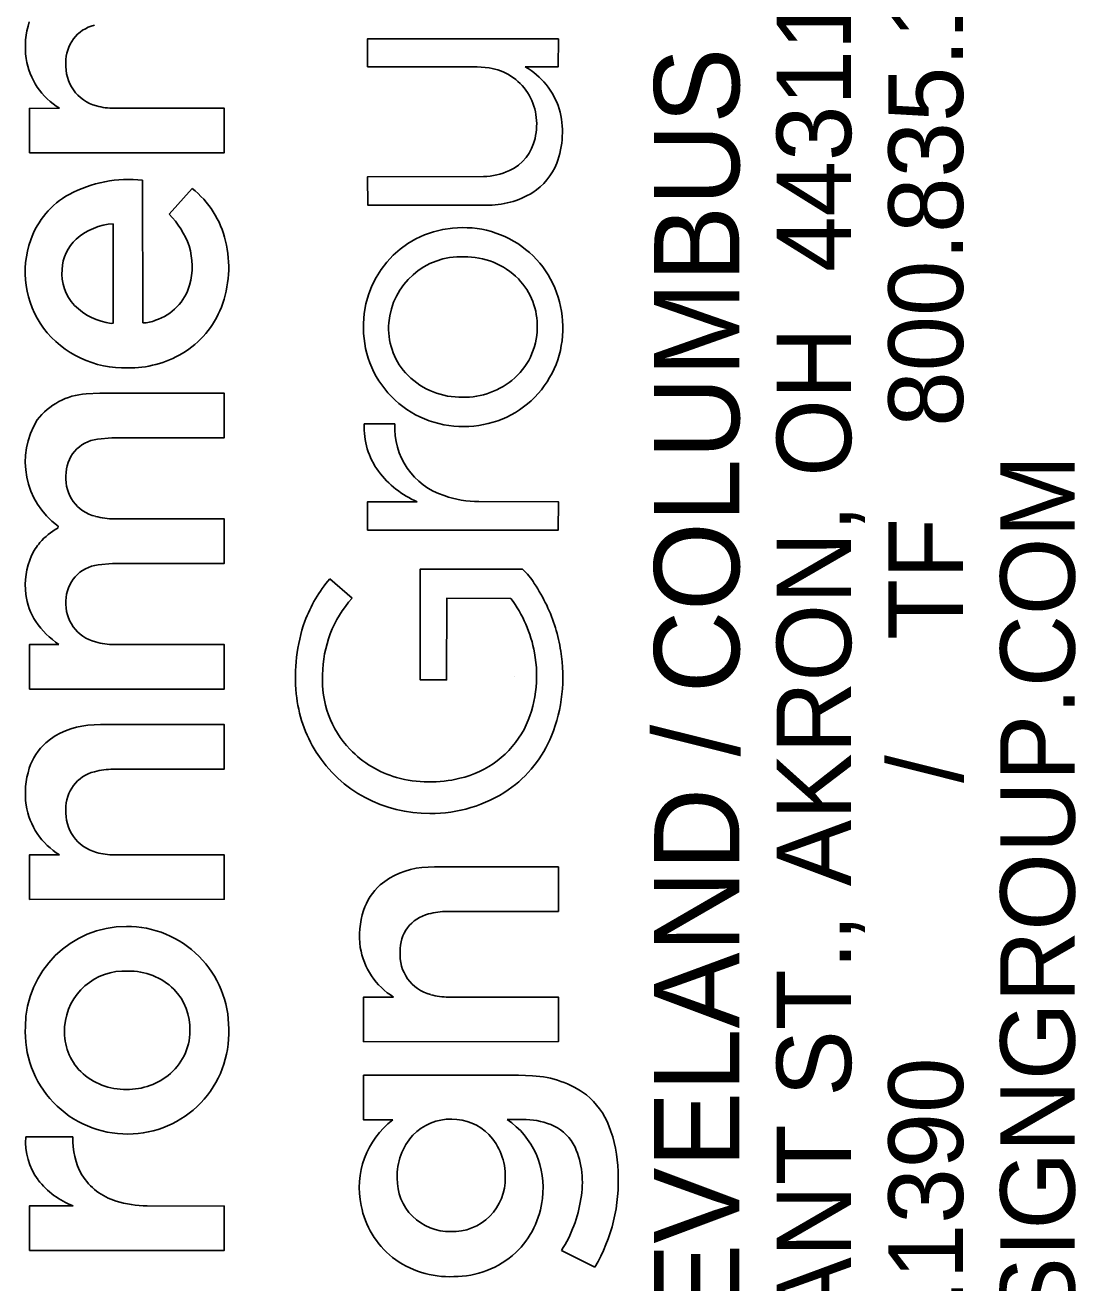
# Model space of a CAD drawing. Extents: x -1.7 to 34, y -55.6 to 22.
# Drawn here: x 32.423 to 33.125, y 3.594 to 4.436 of the extents above; entities that cross this region are included whole.
import ezdxf

# ---------------------------------------------------------------- set-up
doc = ezdxf.new("R2010")
doc.units = 0
doc.layers.add('SH_Data', color=7, linetype='Continuous')

msp = doc.modelspace()

# ---------------------------------------------------------------- linework, layer by layer
at = {"layer": 'SH_Data'}
for p, q in [((32.65152, 4.40801), (32.65153, 4.42672)), ((32.65153, 4.42672), (32.7791, 4.42664)), ((32.7791, 4.42664), (32.77908, 4.40796)), ((32.7249, 4.40796), (32.65152, 4.40801)), ((32.7328, 4.40727), (32.7249, 4.40796)), ((32.77908, 4.40796), (32.75689, 4.40796)), ((32.42542, 4.38016), (32.44552, 4.38021)), ((32.42542, 4.35035), (32.42542, 4.38016)), ((32.48222, 4.38021), (32.55569, 4.38021)), ((32.55569, 4.38021), (32.55571, 4.35045)), ((32.55571, 4.35045), (32.42542, 4.35035)), ((32.65154, 4.33443), (32.72905, 4.3345)), ((32.65165, 4.31543), (32.65154, 4.33443)), ((32.50108, 4.33209), (32.50118, 4.23657)), ((32.51882, 4.30927), (32.53422, 4.32662)), ((32.73073, 4.31543), (32.65165, 4.31543)), ((32.48144, 4.23644), (32.48144, 4.30296)), ((32.48016, 4.23628), (32.48144, 4.23644)), ((32.46329, 4.18915), (32.47259, 4.18968)), ((32.47259, 4.18968), (32.55557, 4.18968)), ((32.55557, 4.18968), (32.55571, 4.15982)), ((32.64932, 4.16907), (32.66978, 4.16907)), ((32.48058, 4.15981), (32.47102, 4.15881)), ((32.55571, 4.15982), (32.48058, 4.15981)), ((32.65152, 4.11699), (32.68476, 4.117)), ((32.65152, 4.098), (32.65152, 4.11699)), ((32.72605, 4.11703), (32.7791, 4.11696)), ((32.7791, 4.11696), (32.77903, 4.098)), ((32.44443, 4.09922), (32.44455, 4.10072)), ((32.48218, 4.10553), (32.55571, 4.10548)), ((32.55571, 4.10548), (32.55571, 4.07568)), ((32.77903, 4.098), (32.65152, 4.098)), ((32.4809, 4.07567), (32.47143, 4.07474)), ((32.55571, 4.07568), (32.4809, 4.07567)), ((32.62636, 4.06548), (32.64114, 4.05241)), ((32.6868, 4.07185), (32.75516, 4.07192)), ((32.6868, 3.99778), (32.6868, 4.07185)), ((32.70448, 4.05241), (32.70432, 3.99775)), ((32.74737, 4.05227), (32.70448, 4.05241)), ((32.42542, 3.99152), (32.42545, 4.02138)), ((32.42545, 4.02138), (32.44515, 4.02138)), ((32.48206, 4.02138), (32.55571, 4.02136)), ((32.55571, 4.02136), (32.55571, 3.99156)), ((32.70432, 3.99775), (32.6868, 3.99778)), ((32.75, 4), (32.75, 4)), ((32.55571, 3.99156), (32.42542, 3.99152)), ((32.46439, 3.96736), (32.47289, 3.96783)), ((32.47289, 3.96783), (32.55571, 3.96783)), ((32.55571, 3.96783), (32.55571, 3.93804)), ((32.55571, 3.93804), (32.4814, 3.93796)), ((32.42542, 3.88066), (32.44552, 3.88071)), ((32.42542, 3.85086), (32.42542, 3.88066)), ((32.48222, 3.88071), (32.55569, 3.88071)), ((32.55569, 3.88071), (32.55571, 3.85096)), ((32.68784, 3.8722), (32.69634, 3.87266)), ((32.69634, 3.87266), (32.77916, 3.87266)), ((32.77916, 3.87266), (32.77917, 3.84287)), ((32.55571, 3.85096), (32.42542, 3.85086)), ((32.77917, 3.84287), (32.70485, 3.8428)), ((32.64888, 3.7855), (32.66897, 3.78555)), ((32.64888, 3.75569), (32.64888, 3.7855)), ((32.70568, 3.78555), (32.77915, 3.78555)), ((32.77915, 3.78555), (32.77917, 3.75579)), ((32.77917, 3.75579), (32.64888, 3.75569)), ((32.6489, 3.70336), (32.64889, 3.73322)), ((32.64889, 3.73322), (32.75236, 3.73322)), ((32.75236, 3.73322), (32.76191, 3.73285)), ((32.66836, 3.70336), (32.6489, 3.70336)), ((32.75763, 3.70356), (32.74487, 3.70361)), ((32.42299, 3.69193), (32.45454, 3.69193)), ((32.42542, 3.64577), (32.45473, 3.64579)), ((32.42542, 3.61593), (32.42542, 3.64577)), ((32.50413, 3.64581), (32.55571, 3.64573)), ((32.55571, 3.64573), (32.55565, 3.61593)), ((32.55565, 3.61593), (32.42542, 3.61593)), ((32.8036, 3.60491), (32.7812, 3.61598))]:
    msp.add_line(p, q, dxfattribs=at)
for points in [[(32.7328, 4.40727), (32.7249, 4.40796), (32.65152, 4.40801), (32.65153, 4.42672), (32.7791, 4.42664), (32.77908, 4.40796), (32.75689, 4.40796)], [(32.42542, 4.35035), (32.42542, 4.38016), (32.44552, 4.38021)], [(32.48222, 4.38021), (32.55569, 4.38021), (32.55571, 4.35045), (32.42542, 4.35035)], [(32.73073, 4.31543), (32.65165, 4.31543), (32.65154, 4.33443), (32.72905, 4.3345)], [(32.50108, 4.33209), (32.50118, 4.23657)], [(32.51882, 4.30927), (32.53422, 4.32662)], [(32.48016, 4.23628), (32.48144, 4.23644), (32.48144, 4.30296)], [(32.46329, 4.18915), (32.47259, 4.18968), (32.55557, 4.18968), (32.55571, 4.15982), (32.48058, 4.15981), (32.47102, 4.15881)], [(32.64932, 4.16907), (32.66978, 4.16907)], [(32.72605, 4.11703), (32.7791, 4.11696), (32.77903, 4.098), (32.65152, 4.098)], [(32.65152, 4.098), (32.65152, 4.11699), (32.68476, 4.117)], [(32.44443, 4.09922), (32.44455, 4.10072)], [(32.48218, 4.10553), (32.55571, 4.10548), (32.55571, 4.07568), (32.4809, 4.07567), (32.47143, 4.07474)], [(32.62636, 4.06548), (32.64114, 4.05241)], [(32.74737, 4.05227), (32.70448, 4.05241), (32.70432, 3.99775), (32.6868, 3.99778), (32.6868, 4.07185), (32.75516, 4.07192)], [(32.42542, 3.99152), (32.42545, 4.02138), (32.44515, 4.02138)], [(32.48206, 4.02138), (32.55571, 4.02136), (32.55571, 3.99156), (32.42542, 3.99152)], [(32.46439, 3.96736), (32.47289, 3.96783), (32.55571, 3.96783), (32.55571, 3.93804), (32.4814, 3.93796)], [(32.42542, 3.85086), (32.42542, 3.88066), (32.44552, 3.88071)], [(32.48222, 3.88071), (32.55569, 3.88071), (32.55571, 3.85096), (32.42542, 3.85086)], [(32.68784, 3.8722), (32.69634, 3.87266), (32.77916, 3.87266), (32.77917, 3.84287), (32.70485, 3.8428)], [(32.64888, 3.75569), (32.64888, 3.7855), (32.66897, 3.78555)], [(32.70568, 3.78555), (32.77915, 3.78555), (32.77917, 3.75579), (32.64888, 3.75569)], [(32.66836, 3.70336), (32.6489, 3.70336), (32.64889, 3.73322), (32.75236, 3.73322), (32.76191, 3.73285)], [(32.75763, 3.70356), (32.74487, 3.70361)], [(32.42299, 3.69193), (32.45454, 3.69193)], [(32.50413, 3.64581), (32.55571, 3.64573), (32.55565, 3.61593), (32.42542, 3.61593)], [(32.42542, 3.61593), (32.42542, 3.64577), (32.45473, 3.64579)], [(32.8036, 3.60491), (32.7812, 3.61598)]]:
    msp.add_lwpolyline(points, dxfattribs=at)
for centre, radius, start, end in [((32.47872, 4.42108), 0.05602, 162.27398, 187.79173), ((32.47872, 4.42108), 0.05602, 162.27398, 187.79173), ((32.47482, 4.41155), 0.02498, 103.68683, 182.21395), ((32.47482, 4.41155), 0.02498, 103.68683, 182.21395), ((32.47027, 4.4209), 0.04763, 188.96462, 238.69865), ((32.47027, 4.4209), 0.04763, 188.96462, 238.69865), ((32.47735, 4.40846), 0.02757, 175.58441, 255.13816), ((32.47735, 4.40846), 0.02757, 175.58441, 255.13816), ((32.72711, 4.36998), 0.03772, 33.50082, 81.32954), ((32.72711, 4.36998), 0.03772, 33.50082, 81.32954), ((32.73239, 4.36485), 0.04959, 17.62209, 60.38974), ((32.73239, 4.36485), 0.04959, 17.62209, 60.38974), ((32.72414, 4.3695), 0.04048, 346.56179, 31.75389), ((32.72414, 4.3695), 0.04048, 346.56179, 31.75389), ((32.48183, 4.42235), 0.04215, 254.08913, 270.52838), ((32.48183, 4.42235), 0.04215, 254.08913, 270.52838), ((32.72343, 4.36415), 0.05838, 339.16197, 15.61485), ((32.72343, 4.36415), 0.05838, 339.16197, 15.61485), ((32.73371, 4.36616), 0.03042, 294.63214, 348.48625), ((32.73371, 4.36616), 0.03042, 294.63214, 348.48625), ((32.739, 4.35901), 0.04201, 303.10391, 338.15613), ((32.739, 4.35901), 0.04201, 303.10391, 338.15613), ((32.72747, 4.38081), 0.04633, 271.95199, 294.08943), ((32.72747, 4.38081), 0.04633, 271.95199, 294.08943), ((32.49176, 4.24874), 0.08387, 83.62118, 118.28448), ((32.49176, 4.24874), 0.08387, 83.62118, 118.28448), ((32.49399, 4.2763), 0.06443, 13.53275, 51.36266), ((32.49399, 4.2763), 0.06443, 13.53275, 51.36266), ((32.47894, 4.27368), 0.05583, 118.82935, 160.62242), ((32.47894, 4.27368), 0.05583, 118.82935, 160.62242), ((32.7321, 4.37256), 0.05715, 268.62699, 301.47779), ((32.7321, 4.37256), 0.05715, 268.62699, 301.47779), ((32.48033, 4.27018), 0.05485, 19.0387, 45.44322), ((32.48033, 4.27018), 0.05485, 19.0387, 45.44322), ((32.4844, 4.26071), 0.04236, 94.01311, 130.88062), ((32.4844, 4.26071), 0.04236, 94.01311, 130.88062), ((32.71435, 4.23484), 0.06552, 89.48213, 178.77752), ((32.71435, 4.23484), 0.06552, 89.48213, 178.77752), ((32.71582, 4.23414), 0.06623, 0.42265, 90.7613), ((32.71582, 4.23414), 0.06623, 0.42265, 90.7613), ((32.48697, 4.27074), 0.06438, 160.52138, 215.78155), ((32.48697, 4.27074), 0.06438, 160.52138, 215.78155), ((32.47703, 4.2709), 0.02985, 132.98553, 177.1802), ((32.47703, 4.2709), 0.02985, 132.98553, 177.1802), ((32.48724, 4.27433), 0.04701, 344.60723, 17.00675), ((32.48724, 4.27433), 0.04701, 344.60723, 17.00675), ((32.48289, 4.27384), 0.0758, 339.35431, 13.37708), ((32.48289, 4.27384), 0.0758, 339.35431, 13.37708), ((32.71397, 4.23244), 0.04846, 87.68827, 175.01696), ((32.71397, 4.23244), 0.04846, 87.68827, 175.01696), ((32.71659, 4.23036), 0.05052, 44.91202, 90.75914), ((32.71659, 4.23036), 0.05052, 44.91202, 90.75914), ((32.47824, 4.26966), 0.03114, 175.00138, 223.2876), ((32.47824, 4.26966), 0.03114, 175.00138, 223.2876), ((32.49895, 4.27177), 0.03504, 288.01084, 343.55364), ((32.49895, 4.27177), 0.03504, 288.01084, 343.55364), ((32.71955, 4.23452), 0.04549, 358.32279, 43.83486), ((32.71955, 4.23452), 0.04549, 358.32279, 43.83486), ((32.48546, 4.27826), 0.04232, 225.06454, 262.79701), ((32.48546, 4.27826), 0.04232, 225.06454, 262.79701), ((32.49548, 4.26982), 0.0626, 300.94393, 338.73223), ((32.49548, 4.26982), 0.0626, 300.94393, 338.73223), ((32.48908, 4.27516), 0.06872, 217.74341, 271.65606), ((32.48908, 4.27516), 0.06872, 217.74341, 271.65606), ((32.50129, 4.25678), 0.02021, 269.70042, 294.87295), ((32.50129, 4.25678), 0.02021, 269.70042, 294.87295), ((32.71483, 4.2334), 0.06606, 177.53728, 270.94524), ((32.71483, 4.2334), 0.06606, 177.53728, 270.94524), ((32.71085, 4.23311), 0.0453, 175.51467, 221.42047), ((32.71085, 4.23311), 0.0453, 175.51467, 221.42047), ((32.71671, 4.23271), 0.06536, 269.30834, 1.67905), ((32.71671, 4.23271), 0.06536, 269.30834, 1.67905), ((32.71931, 4.23374), 0.04572, 308.90382, 359.30947), ((32.71931, 4.23374), 0.04572, 308.90382, 359.30947), ((32.49204, 4.27702), 0.07055, 269.20529, 300.33566), ((32.49204, 4.27702), 0.07055, 269.20529, 300.33566), ((32.71399, 4.23734), 0.05046, 222.66255, 268.37331), ((32.71399, 4.23734), 0.05046, 222.66255, 268.37331), ((32.71567, 4.23859), 0.05178, 266.55312, 308.67253), ((32.71567, 4.23859), 0.05178, 266.55312, 308.67253), ((32.46638, 4.14404), 0.04521, 93.91118, 142.30723), ((32.46638, 4.14404), 0.04521, 93.91118, 142.30723), ((32.47585, 4.14373), 0.05319, 148.28793, 233.9556), ((32.47585, 4.14373), 0.05319, 148.28793, 233.9556), ((32.69878, 4.16662), 0.04952, 177.16211, 216.28024), ((32.69878, 4.16662), 0.04952, 177.16211, 216.28024), ((32.71735, 4.16638), 0.04764, 176.76988, 252.15044), ((32.71735, 4.16638), 0.04764, 176.76988, 252.15044), ((32.47384, 4.13499), 0.02399, 96.75763, 181.6251), ((32.47384, 4.13499), 0.02399, 96.75763, 181.6251), ((32.47577, 4.13241), 0.02597, 175.81573, 256.16716), ((32.47577, 4.13241), 0.02597, 175.81573, 256.16716), ((32.70975, 4.17555), 0.06366, 216.91526, 246.88619), ((32.70975, 4.17555), 0.06366, 216.91526, 246.88619), ((32.7269, 4.19175), 0.07473, 251.13884, 269.34694), ((32.7269, 4.19175), 0.07473, 251.13884, 269.34694), ((32.4817, 4.15053), 0.04501, 254.34629, 270.61033), ((32.4817, 4.15053), 0.04501, 254.34629, 270.61033), ((32.4638, 4.06267), 0.04137, 117.91625, 139.24296), ((32.4638, 4.06267), 0.04137, 117.91625, 139.24296), ((32.46194, 4.06452), 0.03875, 139.52447, 154.84698), ((32.46194, 4.06452), 0.03875, 139.52447, 154.84698), ((32.47144, 4.0612), 0.04877, 156.06382, 187.3493), ((32.47144, 4.0612), 0.04877, 156.06382, 187.3493), ((32.47421, 4.05056), 0.02434, 96.5532, 179.94902), ((32.47421, 4.05056), 0.02434, 96.5532, 179.94902), ((32.70163, 4.00187), 0.09855, 139.79476, 159.13696), ((32.70163, 4.00187), 0.09855, 139.79476, 159.13696), ((32.72498, 4.03937), 0.04438, 30.98913, 47.16099), ((32.72498, 4.03937), 0.04438, 30.98913, 47.16099), ((32.67091, 4.00018), 0.11106, 25.30315, 33.96179), ((32.67091, 4.00018), 0.11106, 25.30315, 33.96179), ((32.46461, 4.05974), 0.04181, 186.5579, 213.38846), ((32.46461, 4.05974), 0.04181, 186.5579, 213.38846), ((32.47608, 4.04863), 0.02628, 175.722, 255.78627), ((32.47608, 4.04863), 0.02628, 175.722, 255.78627), ((32.69899, 4.00079), 0.07753, 138.25804, 179.70064), ((32.69899, 4.00079), 0.07753, 138.25804, 179.70064), ((32.67889, 4.00099), 0.08556, 10.07509, 36.83189), ((32.67889, 4.00099), 0.08556, 10.07509, 36.83189), ((32.6704, 3.99987), 0.11166, 8.80339, 25.33484), ((32.6704, 3.99987), 0.11166, 8.80339, 25.33484), ((32.47886, 4.07078), 0.0598, 214.70433, 235.68724), ((32.47886, 4.07078), 0.0598, 214.70433, 235.68724), ((32.7187, 3.99968), 0.11536, 161.14379, 185.62812), ((32.7187, 3.99968), 0.11536, 161.14379, 185.62812), ((32.48195, 4.06518), 0.0438, 253.66719, 270.14979), ((32.48195, 4.06518), 0.0438, 253.66719, 270.14979), ((32.68425, 4.00057), 0.08036, 333.46689, 11.03668), ((32.68425, 4.00057), 0.08036, 333.46689, 11.03668), ((32.67564, 3.99977), 0.10649, 338.28866, 9.28548), ((32.67564, 3.99977), 0.10649, 338.28866, 9.28548), ((32.68811, 3.99732), 0.06676, 176.66577, 223.6912), ((32.68811, 3.99732), 0.06676, 176.66577, 223.6912), ((32.69336, 3.99699), 0.08987, 185.50773, 212.01294), ((32.69336, 3.99699), 0.08987, 185.50773, 212.01294), ((32.46871, 3.91767), 0.04988, 94.97056, 130.22484), ((32.46871, 3.91767), 0.04988, 94.97056, 130.22484), ((32.69868, 3.99547), 0.0652, 282.88151, 331.81475), ((32.69868, 3.99547), 0.0652, 282.88151, 331.81475), ((32.46348, 3.92602), 0.04016, 132.22383, 161.68229), ((32.46348, 3.92602), 0.04016, 132.22383, 161.68229), ((32.69835, 3.99168), 0.08241, 305.03061, 337.67573), ((32.69835, 3.99168), 0.08241, 305.03061, 337.67573), ((32.69211, 3.99748), 0.08908, 212.70222, 270.71399), ((32.69211, 3.99748), 0.08908, 212.70222, 270.71399), ((32.69045, 4.00011), 0.07039, 224.02147, 253.88), ((32.69045, 4.00011), 0.07039, 224.02147, 253.88), ((32.47872, 3.92158), 0.05602, 162.27398, 187.79173), ((32.47872, 3.92158), 0.05602, 162.27398, 187.79173), ((32.47482, 3.91206), 0.02498, 103.68683, 182.21395), ((32.47482, 3.91206), 0.02498, 103.68683, 182.21395), ((32.48108, 3.89196), 0.04601, 89.60515, 105.33026), ((32.48108, 3.89196), 0.04601, 89.60515, 105.33026), ((32.69318, 4.01254), 0.08309, 254.45353, 283.9512), ((32.69318, 4.01254), 0.08309, 254.45353, 283.9512), ((32.69429, 3.99979), 0.09138, 269.3273, 304.19632), ((32.69429, 3.99979), 0.09138, 269.3273, 304.19632), ((32.47027, 3.92141), 0.04763, 188.96462, 238.69865), ((32.47027, 3.92141), 0.04763, 188.96462, 238.69865), ((32.47735, 3.90897), 0.02757, 175.58441, 255.13816), ((32.47735, 3.90897), 0.02757, 175.58441, 255.13816), ((32.48183, 3.92286), 0.04215, 254.08913, 270.52838), ((32.48183, 3.92286), 0.04215, 254.08913, 270.52838), ((32.69216, 3.82251), 0.04988, 94.97056, 130.22484), ((32.69216, 3.82251), 0.04988, 94.97056, 130.22484), ((32.68694, 3.83085), 0.04016, 132.22383, 161.68229), ((32.68694, 3.83085), 0.04016, 132.22383, 161.68229), ((32.70217, 3.82642), 0.05602, 162.27398, 187.79173), ((32.70217, 3.82642), 0.05602, 162.27398, 187.79173), ((32.69828, 3.81689), 0.02498, 103.68683, 182.21395), ((32.69828, 3.81689), 0.02498, 103.68683, 182.21395), ((32.70453, 3.79679), 0.04601, 89.60515, 105.33026), ((32.70453, 3.79679), 0.04601, 89.60515, 105.33026), ((32.49014, 3.76543), 0.0674, 89.84756, 179.64047), ((32.49014, 3.76543), 0.0674, 89.84756, 179.64047), ((32.49057, 3.76474), 0.0681, 359.54009, 90.21138), ((32.49057, 3.76474), 0.0681, 359.54009, 90.21138), ((32.69372, 3.82624), 0.04763, 188.96462, 238.69865), ((32.69372, 3.82624), 0.04763, 188.96462, 238.69865), ((32.7008, 3.81381), 0.02757, 175.58441, 255.13816), ((32.7008, 3.81381), 0.02757, 175.58441, 255.13816), ((32.48923, 3.76263), 0.0404, 87.04809, 175.57259), ((32.48923, 3.76263), 0.0404, 87.04809, 175.57259), ((32.49204, 3.75999), 0.04299, 45.84264, 90.98008), ((32.49204, 3.75999), 0.04299, 45.84264, 90.98008), ((32.49458, 3.76421), 0.03821, 357.88569, 44.15902), ((32.49458, 3.76421), 0.03821, 357.88569, 44.15902), ((32.70529, 3.82769), 0.04215, 254.08913, 270.52838), ((32.70529, 3.82769), 0.04215, 254.08913, 270.52838), ((32.49083, 3.76209), 0.06819, 176.8344, 270.40384), ((32.49083, 3.76209), 0.06819, 176.8344, 270.40384), ((32.48729, 3.7625), 0.03848, 175.15378, 221.14706), ((32.48729, 3.7625), 0.03848, 175.15378, 221.14706), ((32.49123, 3.76139), 0.06749, 270.06243, 2.37759), ((32.49123, 3.76139), 0.06749, 270.06243, 2.37759), ((32.49446, 3.76318), 0.0383, 308.28936, 359.43468), ((32.49446, 3.76318), 0.0383, 308.28936, 359.43468), ((32.48919, 3.76607), 0.04228, 223.09994, 268.80895), ((32.48919, 3.76607), 0.04228, 223.09994, 268.80895), ((32.49096, 3.7679), 0.04418, 266.56515, 308.06078), ((32.49096, 3.7679), 0.04418, 266.56515, 308.06078), ((32.75907, 3.66789), 0.06503, 53.40344, 87.49062), ((32.75907, 3.66789), 0.06503, 53.40344, 87.49062), ((32.76517, 3.68039), 0.05141, 21.60748, 50.5577), ((32.76517, 3.68039), 0.05141, 21.60748, 50.5577), ((32.70292, 3.65813), 0.05692, 127.37482, 192.22468), ((32.70292, 3.65813), 0.05692, 127.37482, 192.22468), ((32.70693, 3.66927), 0.0346, 88.47302, 136.42562), ((32.70693, 3.66927), 0.0346, 88.47302, 136.42562), ((32.70814, 3.66963), 0.03424, 44.27195, 90.47623), ((32.70814, 3.66963), 0.03424, 44.27195, 90.47623), ((32.71421, 3.65829), 0.05472, 352.1125, 55.92295), ((32.71421, 3.65829), 0.05472, 352.1125, 55.92295), ((32.75666, 3.65725), 0.04633, 65.01687, 88.8011), ((32.75666, 3.65725), 0.04633, 65.01687, 88.8011), ((32.7626, 3.67155), 0.03085, 26.26808, 63.80301), ((32.7626, 3.67155), 0.03085, 26.26808, 63.80301), ((32.73069, 3.66714), 0.08835, 1.15143, 21.3627), ((32.73069, 3.66714), 0.08835, 1.15143, 21.3627), ((32.46616, 3.68882), 0.04329, 175.87313, 216.34747), ((32.46616, 3.68882), 0.04329, 175.87313, 216.34747), ((32.50087, 3.68948), 0.04639, 176.9688, 209.60636), ((32.50087, 3.68948), 0.04639, 176.9688, 209.60636), ((32.71141, 3.66602), 0.0401, 137.46739, 182.33237), ((32.71141, 3.66602), 0.0401, 137.46739, 182.33237), ((32.70368, 3.666), 0.03996, 358.57141, 43.53765), ((32.70368, 3.666), 0.03996, 358.57141, 43.53765), ((32.73565, 3.66154), 0.05953, 349.30734, 23.43071), ((32.73565, 3.66154), 0.05953, 349.30734, 23.43071), ((32.70538, 3.66244), 0.11383, 329.6388, 3.25998), ((32.70538, 3.66244), 0.11383, 329.6388, 3.25998), ((32.47466, 3.69716), 0.05511, 218.09809, 248.7907), ((32.47466, 3.69716), 0.05511, 218.09809, 248.7907), ((32.49514, 3.68814), 0.04079, 211.94466, 253.2028), ((32.49514, 3.68814), 0.04079, 211.94466, 253.2028), ((32.70645, 3.6637), 0.03511, 178.88208, 271.08374), ((32.70645, 3.6637), 0.03511, 178.88208, 271.08374), ((32.70818, 3.66404), 0.03546, 268.27882, 1.55016), ((32.70818, 3.66404), 0.03546, 268.27882, 1.55016), ((32.50465, 3.7165), 0.07069, 252.46555, 269.57296), ((32.50465, 3.7165), 0.07069, 252.46555, 269.57296), ((32.70463, 3.65696), 0.05837, 190.75182, 231.28919), ((32.70463, 3.65696), 0.05837, 190.75182, 231.28919), ((32.70988, 3.65708), 0.05887, 313.74196, 353.8554), ((32.70988, 3.65708), 0.05887, 313.74196, 353.8554), ((32.70738, 3.66334), 0.08771, 327.31495, 351.57478), ((32.70738, 3.66334), 0.08771, 327.31495, 351.57478), ((32.70632, 3.66112), 0.06269, 232.46061, 272.59022), ((32.70632, 3.66112), 0.06269, 232.46061, 272.59022), ((32.70954, 3.65901), 0.06051, 269.6361, 312.70877), ((32.70954, 3.65901), 0.06051, 269.6361, 312.70877)]:
    msp.add_arc(centre, radius, start, end, dxfattribs=at)

# ---------------------------------------------------------------- texts
for s, height, p in [('800.835.1390', 0.0498462, (33.04966, 4.1671)), ('450 GRANT ST., AKRON, OH  44311', 0.0498462, (32.97489, 3.33738)), ('AKRON / CLEVELAND / COLUMBUS', 0.056969, (32.90012, 3.138)), ('ENVDESIGNGROUP.COM', 0.0498462, (33.12443, 3.33738)), ('TF', 0.049846, (33.04966, 4.0246)), ('/  ', 0.049846, (33.04966, 3.92884)), ('330.375.1390', 0.0498462, (33.04966, 3.33738))]:
    msp.add_text(s, height=height, rotation=90, dxfattribs=at).set_placement(p)

doc.saveas('drawing.dxf')
